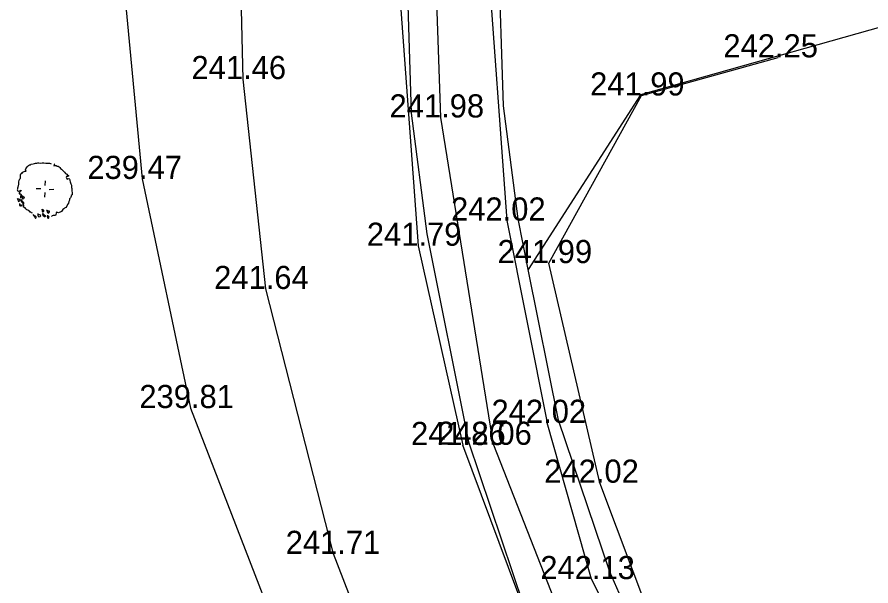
# Model space of a CAD drawing. Extents: x -601589 to -601440, y -1201842 to -1201527.
# Drawn here: x -601527.76 to -601490.84, y -1201639.98 to -1201615.38 of the extents above; entities that cross this region are included whole.
import ezdxf

# ---------------------------------------------------------------- set-up
doc = ezdxf.new("R2010")
doc.units = 0
for name, color, linetype in [('Hranice parcel', 7, 'Continuous'), ('u_hrany', 7, 'Continuous'), ('u_vysadba', 7, 'Continuous'), ('u_vyska', 7, 'Continuous')]:
    doc.layers.add(name, color=color, linetype=linetype)

msp = doc.modelspace()

# ---------------------------------------------------------------- linework, layer by layer
at = {"layer": 'Hranice parcel'}
for points in [[(-601518.5, -1201574.62), (-601510.22, -1201581.07), (-601510.94, -1201612.53), (-601510.72, -1201619.53), (-601510.05, -1201624.75), (-601508.24, -1201633.75), (-601505.86, -1201640.82), (-601502.47, -1201648.58), (-601498.5, -1201656.04), (-601493.62, -1201663.46), (-601488.75, -1201670.45), (-601479.72, -1201682.69), (-601461.88, -1201705.09), (-601445.87, -1201723.83)], [(-601465.64, -1201608.8), (-601500.81, -1201618.74), (-601505.66, -1201626.3)], [(-601505.66, -1201626.3), (-601506.1, -1201624.1), (-601506.73, -1201619.21), (-601506.94, -1201612.51), (-601506.89, -1201610.28)], [(-601460.43, -1201700.48), (-601476.54, -1201680.26), (-601485.5, -1201668.12), (-601490.31, -1201661.22), (-601495.06, -1201653.99), (-601498.9, -1201646.76), (-601502.13, -1201639.37), (-601504.35, -1201632.81), (-601505.66, -1201626.3)]]:
    msp.add_lwpolyline(points, dxfattribs=at)
at = {"layer": 'u_hrany'}
for points in [[(-601505.167, -1201526.653), (-601505.37, -1201547.09), (-601506.1, -1201561.67), (-601507, -1201580.71), (-601507.44, -1201612.51), (-601506.59, -1201624.18), (-601504.84, -1201632.93)], [(-601514.2, -1201569.51), (-601517.03, -1201570.93), (-601522.49, -1201584.67), (-601523.6, -1201596.8), (-601523.78, -1201607.28), (-601522.35, -1201622.38), (-601520.26, -1201632.29), (-601514.11, -1201648.21), (-601507.05, -1201660.77), (-601502.96, -1201664.86), (-601510.13, -1201648.82), (-601514.08, -1201638.6), (-601517, -1201627.14), (-601517.98, -1201618.06), (-601518.55, -1201594.5), (-601514.93, -1201583.59), (-601509.76, -1201580.82)], [(-601507.17, -1201633.88), (-601509.44, -1201619.72), (-601509.7, -1201612.19), (-601509.76, -1201580.82), (-601509.75, -1201574.25)], [(-601514.93, -1201583.59), (-601511.33, -1201590.16), (-601511.4, -1201611.89), (-601510.42, -1201625.27), (-601508.49, -1201633.89)], [(-601500.77, -1201618.77), (-601494.85, -1201617.12)], [(-601460.33, -1201700.35), (-601477.02, -1201679.01), (-601490.59, -1201659.41), (-601493.47, -1201654.35), (-601500.4, -1201641.28), (-601502.56, -1201635.52), (-601504.77, -1201626.02), (-601500.77, -1201618.77)], [(-601443.32, -1201721.42), (-601460.41, -1201701.5), (-601476.94, -1201680.56), (-601485.91, -1201668.41), (-601495.49, -1201654.25), (-601502.92, -1201639.69), (-601504.84, -1201632.93)], [(-601502.92, -1201648.81), (-601508.49, -1201633.89)], [(-601507.17, -1201633.88), (-601501.63, -1201648), (-601497.69, -1201655.55), (-601488, -1201669.96), (-601478.86, -1201682.08), (-601462.72, -1201703.16), (-601444.89, -1201723.91)]]:
    msp.add_lwpolyline(points, dxfattribs=at)
at = {"layer": 'u_vysadba'}
for points in [[(-601527.548, -1201622.121), (-601527.546, -1201622.091), (-601527.486, -1201622.065), (-601527.456, -1201622.052), (-601527.426, -1201622.039), (-601527.397, -1201622.041), (-601527.368, -1201622.042), (-601527.381, -1201622.012), (-601527.394, -1201621.982), (-601527.377, -1201621.939), (-601527.36, -1201621.896), (-601527.329, -1201621.854), (-601527.298, -1201621.826), (-601527.267, -1201621.799), (-601527.222, -1201621.772), (-601527.178, -1201621.774), (-601527.147, -1201621.746), (-601527.073, -1201621.721), (-601527.013, -1201621.71), (-601526.969, -1201621.697), (-601526.911, -1201621.7), (-601526.866, -1201621.688), (-601526.822, -1201621.69), (-601526.749, -1201621.694), (-601526.675, -1201621.683), (-601526.602, -1201621.687), (-601526.515, -1201621.692), (-601526.427, -1201621.697), (-601526.354, -1201621.7), (-601526.311, -1201621.717), (-601526.283, -1201621.733)], [(-601526.136, -1201621.727), (-601526.152, -1201621.755), (-601526.154, -1201621.784), (-601526.17, -1201621.813), (-601526.125, -1201621.8), (-601526.096, -1201621.802), (-601526.067, -1201621.803), (-601526.024, -1201621.82), (-601525.98, -1201621.823), (-601525.938, -1201621.854), (-601525.91, -1201621.885), (-601525.883, -1201621.93), (-601525.841, -1201621.962), (-601525.785, -1201622.009), (-601525.743, -1201622.055), (-601525.716, -1201622.086), (-601525.675, -1201622.146), (-601525.618, -1201622.179), (-601525.576, -1201622.21), (-601525.533, -1201622.227), (-601525.534, -1201622.256)], [(-601527.548, -1201622.121), (-601527.548, -1201622.135), (-601527.595, -1201622.177), (-601527.625, -1201622.204), (-601527.628, -1201622.248), (-601527.63, -1201622.292), (-601527.633, -1201622.35), (-601527.65, -1201622.393), (-601527.666, -1201622.422), (-601527.682, -1201622.45), (-601527.7, -1201622.508), (-601527.701, -1201622.537), (-601527.705, -1201622.595), (-601527.707, -1201622.639), (-601527.708, -1201622.669), (-601527.727, -1201622.741), (-601527.744, -1201622.784), (-601527.746, -1201622.828), (-601527.762, -1201622.856), (-601527.749, -1201622.886), (-601527.706, -1201622.903), (-601527.617, -1201622.878), (-601527.587, -1201622.865), (-601527.619, -1201622.922), (-601527.65, -1201622.95), (-601527.666, -1201622.978), (-601527.669, -1201623.022), (-601527.639, -1201623.024), (-601527.596, -1201623.026), (-601527.582, -1201623.056), (-601527.599, -1201623.099), (-601527.616, -1201623.127), (-601527.618, -1201623.171), (-601527.62, -1201623.215)], [(-601525.534, -1201622.256), (-601525.579, -1201622.269), (-601525.623, -1201622.281), (-601525.639, -1201622.309), (-601525.626, -1201622.339), (-601525.6, -1201622.385), (-601525.57, -1201622.372), (-601525.525, -1201622.359), (-601525.497, -1201622.39), (-601525.484, -1201622.42), (-601525.486, -1201622.449), (-601525.46, -1201622.509), (-601525.447, -1201622.554), (-601525.435, -1201622.598), (-601525.408, -1201622.644), (-601525.41, -1201622.673), (-601525.412, -1201622.717), (-601525.414, -1201622.746), (-601525.401, -1201622.79), (-601525.39, -1201622.85), (-601525.393, -1201622.908), (-601525.381, -1201622.967), (-601525.383, -1201622.996), (-601525.384, -1201623.026), (-601525.387, -1201623.069), (-601525.418, -1201623.097), (-601525.419, -1201623.126), (-601525.436, -1201623.169), (-601525.452, -1201623.198), (-601525.498, -1201623.239), (-601525.501, -1201623.298), (-601525.519, -1201623.355), (-601525.537, -1201623.427), (-601525.584, -1201623.484), (-601525.617, -1201623.555), (-601525.65, -1201623.612), (-601525.71, -1201623.638), (-601525.74, -1201623.666), (-601525.787, -1201623.707), (-601525.818, -1201623.749), (-601525.835, -1201623.792), (-601525.895, -1201623.819), (-601525.94, -1201623.831), (-601525.969, -1201623.844), (-601526.013, -1201623.827), (-601526.056, -1201623.81), (-601526.072, -1201623.853), (-601526.09, -1201623.911), (-601526.107, -1201623.954), (-601526.152, -1201623.966), (-601526.195, -1201623.964)], [(-601526.548, -1201622.662), (-601526.537, -1201622.458)], [(-601526.732, -1201622.813), (-601526.936, -1201622.803)], [(-601526.564, -1201622.969), (-601526.575, -1201623.173)], [(-601526.381, -1201622.832), (-601526.176, -1201622.828)], [(-601527.752, -1201623.208), (-601527.739, -1201623.238), (-601527.726, -1201623.283), (-601527.713, -1201623.313), (-601527.715, -1201623.342), (-601527.686, -1201623.358), (-601527.656, -1201623.33), (-601527.609, -1201623.289), (-601527.639, -1201623.287), (-601527.681, -1201623.256), (-601527.724, -1201623.239)], [(-601527.594, -1201623.275), (-601527.553, -1201623.321), (-601527.511, -1201623.367), (-601527.469, -1201623.399)], [(-601527.469, -1201623.399), (-601527.498, -1201623.397), (-601527.527, -1201623.396), (-601527.556, -1201623.394), (-601527.569, -1201623.364), (-601527.568, -1201623.335), (-601527.581, -1201623.305)], [(-601527.569, -1201623.086), (-601527.572, -1201623.13), (-601527.559, -1201623.16), (-601527.546, -1201623.204), (-601527.533, -1201623.234), (-601527.504, -1201623.236), (-601527.488, -1201623.207), (-601527.428, -1201623.181), (-601527.471, -1201623.164), (-601527.499, -1201623.148), (-601527.556, -1201623.116)], [(-601527.662, -1201623.447), (-601527.652, -1201623.535), (-601527.608, -1201623.538), (-601527.579, -1201623.539), (-601527.534, -1201623.527), (-601527.592, -1201623.509), (-601527.636, -1201623.507), (-601527.649, -1201623.477)], [(-601527.098, -1201623.858), (-601527.141, -1201623.841), (-601527.169, -1201623.824), (-601527.198, -1201623.823), (-601527.225, -1201623.778), (-601527.254, -1201623.761), (-601527.296, -1201623.73), (-601527.339, -1201623.713), (-601527.38, -1201623.667), (-601527.408, -1201623.636), (-601527.48, -1201623.603), (-601527.477, -1201623.559), (-601527.475, -1201623.515), (-601527.488, -1201623.485), (-601527.516, -1201623.469), (-601527.485, -1201623.427), (-601527.456, -1201623.429)], [(-601526.693, -1201623.689), (-601526.683, -1201623.762), (-601526.656, -1201623.808), (-601526.611, -1201623.795), (-601526.61, -1201623.766), (-601526.608, -1201623.737), (-601526.651, -1201623.72), (-601526.68, -1201623.704)], [(-601526.491, -1201623.729), (-601526.464, -1201623.789), (-601526.452, -1201623.833), (-601526.424, -1201623.864), (-601526.394, -1201623.851), (-601526.363, -1201623.809), (-601526.361, -1201623.779), (-601526.405, -1201623.777), (-601526.434, -1201623.761), (-601526.462, -1201623.745), (-601526.491, -1201623.743)], [(-601527.086, -1201623.917), (-601526.99, -1201624.039), (-601526.963, -1201624.084), (-601526.932, -1201624.042), (-601526.93, -1201624.013), (-601526.959, -1201623.997), (-601527.002, -1201623.98), (-601527.03, -1201623.964), (-601527.059, -1201623.947)], [(-601526.864, -1201623.87), (-601526.868, -1201623.943), (-601526.856, -1201623.987), (-601526.828, -1201624.018), (-601526.769, -1201624.007), (-601526.738, -1201623.979), (-601526.751, -1201623.949), (-601526.794, -1201623.932), (-601526.837, -1201623.915)], [(-601526.659, -1201623.866), (-601526.575, -1201623.944), (-601526.547, -1201623.96), (-601526.534, -1201623.99), (-601526.564, -1201624.018), (-601526.594, -1201624.016), (-601526.607, -1201623.986), (-601526.634, -1201623.941), (-601526.661, -1201623.91)], [(-601526.46, -1201623.979), (-601526.449, -1201624.053), (-601526.436, -1201624.083), (-601526.406, -1201624.07), (-601526.375, -1201624.028), (-601526.402, -1201623.997), (-601526.431, -1201623.981), (-601526.46, -1201623.979)], [(-601526.195, -1201623.964), (-601526.24, -1201623.976), (-601526.271, -1201624.004)]]:
    msp.add_lwpolyline(points, dxfattribs=at)

# ---------------------------------------------------------------- texts
at = {"layer": 'u_vyska'}
for s, p in [('242.25', (-601497.224, -1201617.12)), ('241.46', (-601520.222, -1201618.06)), ('241.99', (-601502.987, -1201618.77)), ('241.98', (-601511.659, -1201619.72)), ('239.47', (-601524.724, -1201622.38)), ('242.02', (-601508.999, -1201624.18)), ('241.79', (-601512.639, -1201625.27)), ('241.99', (-601506.987, -1201626.02)), ('241.64', (-601519.242, -1201627.14)), ('239.81', (-601522.476, -1201632.29)), ('242.02', (-601507.249, -1201632.93)), ('241.86', (-601510.728, -1201633.89)), ('242.06', (-601509.598, -1201633.88)), ('242.02', (-601504.969, -1201635.52)), ('241.71', (-601516.148, -1201638.6)), ('242.13', (-601505.14, -1201639.69))]:
    msp.add_text(s, height=1, dxfattribs=at).set_placement(p)

doc.saveas('drawing.dxf')
